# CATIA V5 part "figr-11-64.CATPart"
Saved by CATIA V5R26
Part number: Part1
Bounding box of the stored display mesh (mm): x -54 to 54, y -91.936 to 93.838, z -12.649 to 110.643
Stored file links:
  D:\_Deepak\CATIA\CATIA V5-6R2016_Deepak\Resources\Part files\Partfiles\c11_catia_v5_6r2016_prt\figr-11-64.CATPart
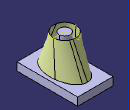
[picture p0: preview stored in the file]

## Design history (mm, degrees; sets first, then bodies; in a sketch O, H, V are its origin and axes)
Set1
  Loft1: Sections (Sketch4; Sketch3)
Body1 (main body)
  Sketch1 on yz-plane, origin (0, 0, 0), H (0, 1, 0), V (0, 0, 1)
    point P1 (93.8379, 11.643)
    line L1 (93.8379, 11.643) -> (93.8379, -12.6487)
    line L2 (93.8379, -12.6487) -> (-91.9362, -12.6487)
    line L3 (-91.9362, -12.6487) -> (-91.9362, 11.643)
    line L4 (-91.9362, 11.643) -> (93.8379, 11.643)
    point P5 (93.8379, 11.643)
    vertical: L1 V, L3 V
    horizontal: L2 H, L4 H
    coincidence: P5 P1
  Pad1: profile Sketch1, direction (1, 0, 0), length 54, mirrored extent
  Sketch2 on face of Pad1, origin (0, 0, 11.643), H (1, 0, 0), V (0, 1, 0)
    circle A1 centre (0, 0) radius 16.7533
    point P1 (16.7533, 0)
    coincidence: A1 P1, P1 H
  Pad2: profile Sketch2, direction (0, 0, 1), length 99
  Sketch3 on face of Pad2, origin (0, 0, 110.643), H (1, 0, 0), V (0, 1, 0)
    point P1 (0, 42.8937)
    point P2 (33.9651, 0)
    projected circle E1 centre (0, 0) radius 16.7533 from edge [face of Pad2 | face of Pad2]
    circle A1 centre (0, 0) radius 33.9651
    point P3 (0, 33.9651)
    coincidence: P1 V, P2 H, A1 P2, A1 P3, P3 V
  Sketch4 on face of Pad1, origin (0, 0, 11.643), H (1, 0, 0), V (0, 1, 0)
    ellipse A1 centre (0, 0) semi-axes 69.9141, 43.1918 rotation 90
    point P1 (0, 69.9141)
    point P2 (43.1918, 0)
    coincidence: P1 V, P2 H, A1 P1, A1 P2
